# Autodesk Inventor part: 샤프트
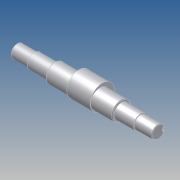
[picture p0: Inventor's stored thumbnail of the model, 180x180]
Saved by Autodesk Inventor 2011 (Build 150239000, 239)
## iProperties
Created: 2013-06
Part Number: 샤프트
Document SubType Name: Modeling
Designer: SeoGD™[esajin.kr]
Density: 1 g/cm^3
Mass: 168.947 g
Surface Area: 248.524 cm^2
Volume: 168.947 cm^3
Author: SeoGD™[esajin.kr]
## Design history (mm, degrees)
sketch "스케치1"
  geometry: L1 (-20.5, -41.331)-(-20.5, 32.669) reference; L2 (7.5, -30.031)-(7.5, 21.369) reference; L3 (135.5, -30.331)-(135.5, 21.669) reference; L4 (121.5, 21.369)-(121.5, -30.031) reference; L5 (184.5, -4.331)-(-57.5, -4.331); L6 (184.5, -4.331)-(184.5, 6.669); L7 (154.5, 8.169)-(121.5, 8.169); L8 (121.5, 8.169)-(121.5, 11.669); L9 (121.5, 11.669)-(7.5, 11.669); L10 (7.5, 11.669)-(7.5, 8.169); L11 (7.5, 8.169)-(-27.5, 8.169); L12 (-27.5, 8.169)-(-27.5, 6.669); L13 (-27.5, 6.669)-(-57.5, 6.669); L14 (-57.5, 6.669)-(-57.5, -4.331); L15 (154.5, 8.169)-(154.5, 6.669); L16 (154.5, 6.669)-(184.5, 6.669); C1 r 32.5 at (64.5, -4.331) reference; 1 further point
  constraints: 24 end point, 8 perpendicular, 5 point on line, 3 parallel, 2 collinear
  dimensions: "d1" = 25 diameter of L11 L5; "d2" = 32 diameter of L9 L5; "d3" = 22 diameter of L13 L5; "d4" = 35 distance of L10.end L11.end; "d5" = 30 distance of L12.end L13.end; "d15" = 33 distance of L7.start L7.end; "d26" = 30 distance of L15.end L6.end
revolve "회전1" sketch "스케치1" stored, may be unused: angle "d6" = 90 deg
node "작업 평면1"
sketch "스케치2"
  geometry: C1 r 16 at (0, 0) reference; C2 r 16 at (0, 0) reference; C3 r 20.75 at (0, 4); C4 r 16 at (0, 0) reference; 1 further point
  constraints: 1 centre point, 1 vertical alignment
  dimensions: "d8" = 41.5 diameter of C3; "d25" = 4 distance of C3.centre C1.centre
extrude "돌출1" join sketch "스케치2" stored distance "d9" = 40; taper "d10" = 0 deg
chamfer "모따기1" distance "d11" = 1; stored, may be unused: second distance "d12" = 2, angle "d13" = 45 deg
node "작업 평면2"
sketch "스케치3"
  geometry: L1 (-15, -10)-(-15, 10) reference; L2 (-15, 3)-(0, 3); L3 (0, -3)-(-15, -3); A1 r 3 centre (0, 0) between (0, -3) and (0, 3); 2 further points
  constraints: 4 end point, 2 perpendicular, 2 point on circle, 2 point on line, 2 tangent, 1 centre point, 1 horizontal alignment, 1 midpoint
  dimensions: "d16" = 18 dimension on A1 L1; "d17" = 6 distance between parallel lines of L3 L2
extrude "돌출2" cut sketch "스케치3" distance "d18" = 3.5; taper "d19" = 0 deg
node "작업 평면3"
node "솔리드1"
mirror "대칭1"
node "참조1"
node "참조2"
node "참조3"
node "참조4"
node "참조5"
node "투영된 루프1"
